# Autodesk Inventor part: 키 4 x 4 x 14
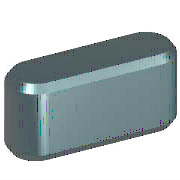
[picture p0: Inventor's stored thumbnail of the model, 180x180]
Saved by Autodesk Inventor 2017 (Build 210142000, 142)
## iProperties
IsCustomPart: 1
Created: 2012-02
Part Number: 키 4 x 4 x 14
Material: 강철, 연강
Description: 키 및 해당 키홈
Document SubType Name: Modeling
Standard: KS B 1311
Designer: mduedu
Standards Organization: KS
Language: ko-KR
Size Designation: 4 x 4 x 12
Categories: <MemberInstance><Categories><Category DisplayName="샤프트 부품" InternalName="7f7aeb1f-a693-4053-b835-cee3144e0d98" Mnemonic="SHFT"><Category DisplayName="키" Interna
Density: 1 g/cm^3
Appearance: 노란색
Author: mduedu
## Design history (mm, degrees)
workplane "Work Plane1"
workplane "Work Plane2"
sketch "스케치1"
  geometry: L1 (2, 2)-(12, 2); L2 (12, -2)-(2, -2); L3 (0, 8.8)-(0, -3.8) reference; L4 (-2.4, 0)-(14.4, 0) reference; L5 (14, 0)-(14, 7); A1 r 2 centre (2, 0) between (2, 2) and (2, -2); A2 r 2 centre (12, 0) between (12, -2) and (12, 2)
  constraints: 6 end point, 5 point on circle, 4 tangent, 3 point on line, 2 centre point, 1 horizontal, 1 parallel, 1 perpendicular
  dimensions: "d0" = 2 radius of A1 (= 0.5 x PB); "d13" = 2 radius of A2 (= 0.5 x PB); "d14" = 14 distance between parallel lines of L5 L3 (= NLG)
extrude "본체1" new body sketch "스케치1" taper "d3" = 0 deg; stored distance "d4" = 10
workplane "Work Plane3"
body "Solid1"
chamfer "모따기1" distance "d8" = 0.25 (= PHH); stored, may be unused: second distance "d9" = 0.25 (= PHH), angle "d15" = 45 deg
other parameters: "d1" = -2.5 (= -PNT), "d2" = 1.5 (= PH - PNT), "NLG" = 14 [user parameter; used in 3 equation terms], "PB" = 4 [user parameter; used in 2 equation terms], "PNT" = 2.5 [user parameter; used in 2 equation terms], "PH" = 4 [user parameter; used in 1 equation term], "PHH" = 0.25 [user parameter; used in 2 equation terms], "d10" = 0, "d16" = 0, "d17" = 0, "d18" = 0, "PLB2" = 14 (= NLG) [user parameter], "WDMAX" = 12 [user parameter], "PLB1" = 14 (= NLG) [user parameter], "RR" = 0.08 [user parameter], "PUEB" = 1.8 [user parameter]
